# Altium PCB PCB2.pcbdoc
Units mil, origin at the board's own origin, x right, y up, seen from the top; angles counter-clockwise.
Board outline 2783.42 x 2077.01 mil, 2 copper layers (Top Layer, Bottom Layer), stack 62.206 mil thick; 55 components, 70 nets, 239 pads, 88 vias.
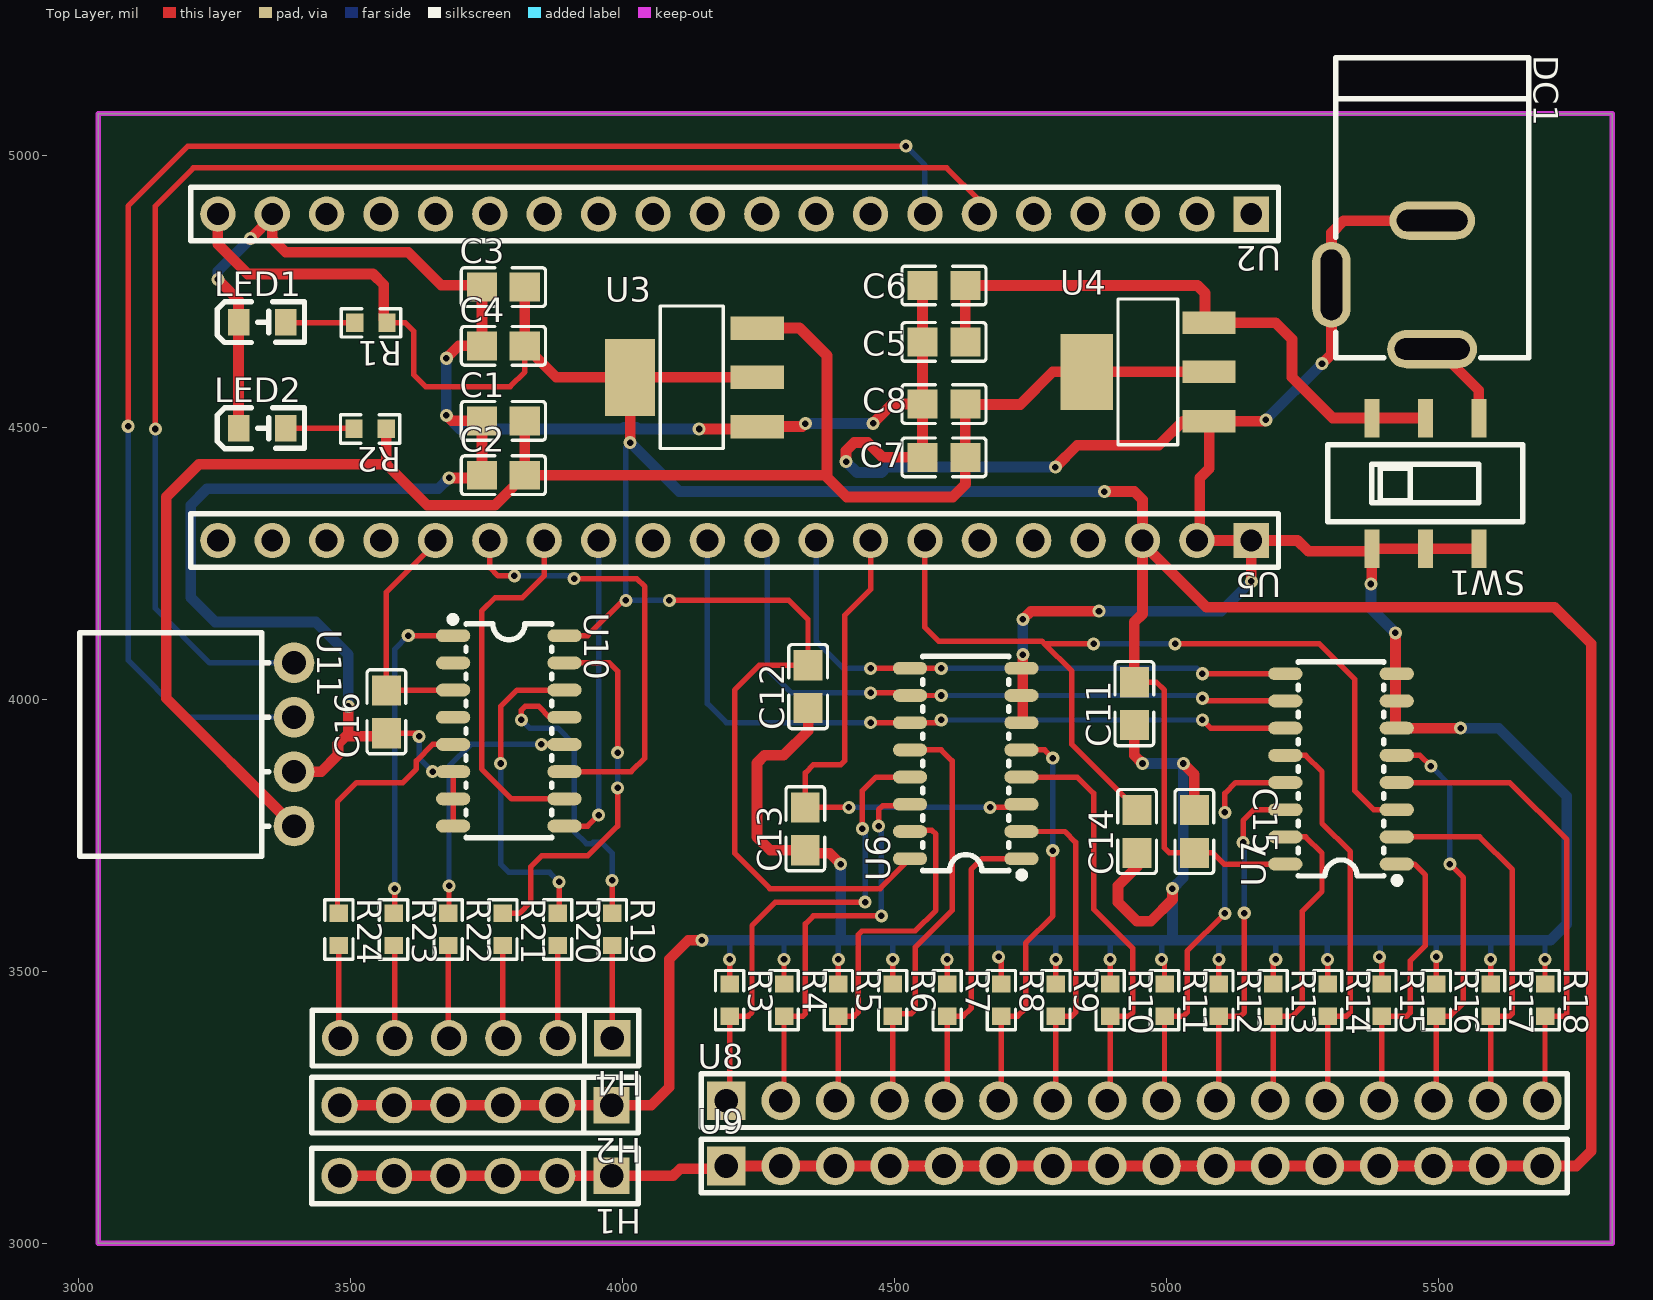
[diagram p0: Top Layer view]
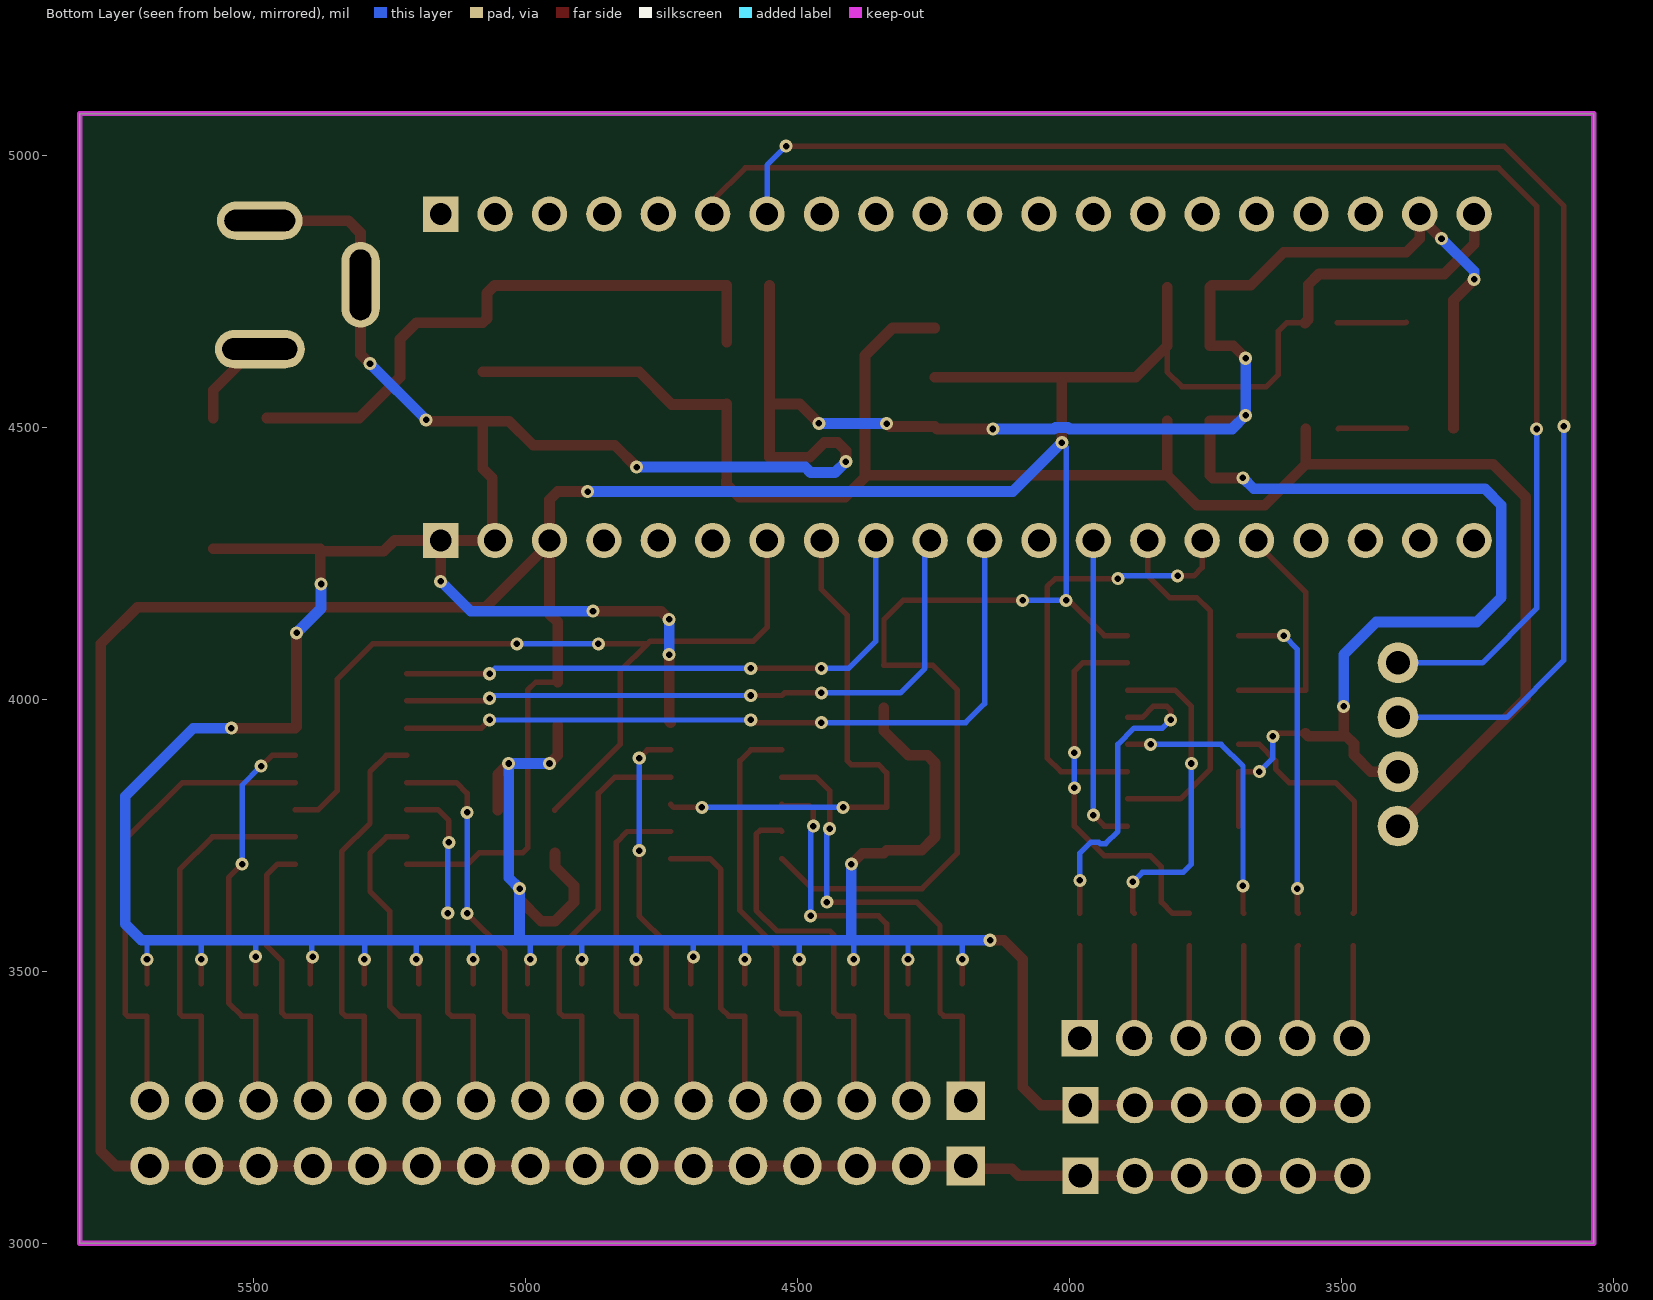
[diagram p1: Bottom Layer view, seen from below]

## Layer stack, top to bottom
Top Solder Mask Layer: solder mask 0.394, Dk 3.3
Top Layer: signal copper 1.379
Dielectric1: surface 59.449, FR4, Dk 4.5
Bottom Layer: signal copper 1.378
Bottom Solder Mask Layer: solder mask 0.394, Dk 3.3

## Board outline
3036.06,5077.01 3036.06,3000 5819.48,3000 5819.48,5077.01

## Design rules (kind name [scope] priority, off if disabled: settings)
BoardOutlineClearance copperThickness1oz [All] p0: genericclearance=10 ignorepadtopadclearanceinfootprint=FALSE except(0: Arc-SplitContinuation Track-SplitContinuation SMDPad-SplitContinuation THPad-SplitContinuation Via-SplitContinuation Fill-SplitContinuation Poly-SplitContinuation Region-SplitContinuation Text-SplitContinuation)
BoardOutlineClearance copperThickness2oz [All] p0: genericclearance=10 ignorepadtopadclearanceinfootprint=FALSE except(0: Arc-SplitContinuation Track-SplitContinuation SMDPad-SplitContinuation THPad-SplitContinuation Via-SplitContinuation Fill-SplitContinuation Poly-SplitContinuation Region-SplitContinuation Text-SplitContinuation)
BoardOutlineClearance otherClearance [All] p0: genericclearance=10 ignorepadtopadclearanceinfootprint=FALSE except(0: Arc-SplitContinuation Track-SplitContinuation SMDPad-SplitContinuation THPad-SplitContinuation Via-SplitContinuation Fill-SplitContinuation Poly-SplitContinuation Region-SplitContinuation Text-SplitContinuation)
Clearance copperThickness1oz [All] p1: gap=7 ignorepadtopadclearanceinfootprint=FALSE
Clearance copperThickness2oz [All] p1: gap=7 ignorepadtopadclearanceinfootprint=FALSE
Clearance otherClearance [All] p1: gap=7 ignorepadtopadclearanceinfootprint=FALSE
DiffPairsRouting differentialPair [All] p1: maxuncoupledlength=10 minlimit=6 maxlimit=Infinity mostfreqgap=6 toplayer_minwidth=5 toplayer_prefwidth=10 toplayer_maxwidth=100 bottomlayer_minwidth=5 bottomlayer_prefwidth=10 bottomlayer_maxwidth=100
PasteMaskExpansion pasteMaskExpansion [All] p1: expansion=0
PlaneConnect innerPlane [All] p1: planeconnectstyle=Relief reliefexpansion=20 reliefentries=4 reliefconductorwidth=10 reliefairgap=10
PolygonConnect copperRegion [All] p1: connectstyle=Relief reliefentries=4 reliefconductorwidth=10 polygonreliefangle="90 Angle" airgapwidth=10
RoutingVias viaSize [All] p1: viastyle="Through Hole" holewidth=12.0078 minholewidth=11.811 maxholewidth=248.0314 width=12.0078 minwidth=11.811 maxwidth=248.0314
SolderMaskExpansion solderMaskExpansion [IsVia] p1: useseparateexpansions=TRUE expansion=-1000 expansionbottom=-1000
SolderMaskExpansion solderMaskExpansion [All] p2: useseparateexpansions=TRUE expansion=2 expansionbottom=2
Width copperThickness1oz [All] p1: maxlimit=100 minlimit=5 preferedwidth=10
Width copperThickness2oz [All] p1: maxlimit=100 minlimit=8 preferedwidth=10

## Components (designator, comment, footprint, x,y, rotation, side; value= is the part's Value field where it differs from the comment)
C1 "10uF" C0805 3781.06,4512.01 r0 top
C2 "100nF" C0805 3781.06,4412.01 r0 top
C3 "10uF" C0805 3781.06,4757.86 r0 top
C4 "100nF" C0805 3781.06,4649.93 r0 top
C5 "10uF" C0805 4591.06,4657.01 r0 top
C6 "100nF" C0805 4591.06,4760.78 r0 top
C7 "10uF" C0805 4591.06,4444.93 r0 top
C8 "100nF" C0805 4591.06,4542.86 r0 top
C11 "10nF" C0805 4941.06,3992.01 r90 top
C12 "10nF" C0805 4341.37,4023.33 r90 top
C13 "10nF" C0805 4336.06,3762.01 r90 top
C14 "10nF" C0805 4946.06,3757.01 r90 top
C15 "100nF" C0805 5051.38,3756.93 r270 top
C16 "100nF" C0805 3566.06,3977.01 r90 top
DC1 "DC-005-5A-2.0" DC-IN-TH_DC-005-5A-2.0 5396.06,4762.01 r270 top
H1 "PZ254V-11-06P" HDR-TH_6P-P2.54-V-M 3729.86,3123.84 r180 top
H2 "PZ254V-11-06P" HDR-TH_6P-P2.54-V-M 3729.86,3253.84 r180 top
H4 "PZ254V-11-06P" HDR-TH_6P-P2.54-V-M 3731.06,3377.01 r180 top
LED1 "" LED_0805 3339.43,4693.25 r0 top
LED2 "" LED_0805 3339.43,4498.25 r0 top
R1 "1K" R0603 3537.57,4692.01 r180 top
R2 "1K" R0603 3536.06,4497.01 r180 top
R3 "24K" R0603 4197.01,3447.09 r270 top
R4 "24K" R0603 4296.95,3447.09 r270 top
R5 "24K" R0603 4396.89,3447.09 r270 top
R6 "24K" R0603 4496.82,3447.09 r270 top
R7 "24K" R0603 4596.76,3447.09 r270 top
R8 "24K" R0603 4696.7,3447.09 r270 top
R9 "24K" R0603 4796.63,3447.09 r270 top
R10 "24K" R0603 4896.57,3447.09 r270 top
R11 "24K" R0603 4996.51,3447.09 r270 top
R12 "24K" R0603 5096.44,3447.09 r270 top
R13 "24K" R0603 5196.38,3447.09 r270 top
R14 "24K" R0603 5296.32,3447.09 r270 top
R15 "24K" R0603 5396.25,3447.09 r270 top
R16 "24K" R0603 5496.19,3447.09 r270 top
R17 "24K" R0603 5596.12,3447.09 r270 top
R18 "24K" R0603 5696.06,3447.09 r270 top
R19 "1K" R0603 3981.37,3576.86 r270 top
R20 "1K" R0603 3880.78,3576.86 r270 top
R21 "1K" R0603 3780.19,3576.86 r270 top
R22 "1K" R0603 3679.6,3576.86 r270 top
R23 "1K" R0603 3579.01,3576.86 r270 top
R24 "1K" R0603 3478.41,3576.86 r270 top
SW1 "SS-3235S-L1" SW-SMD_SS-3235S-LX 5476.06,4397.01 r180 top
U2 "KH-2.54FH-1X20P-H8.5" HDR-TH_20P-P2.54-V-F-2 4206.06,4892.01 r180 top
U3 "AMS1117-3.3" SOT-223-3_L6.5-W3.4-P2.30-LS7.0-BR 4131.06,4592.01 r0 top
U4 "AMS1117-5.0" SOT-223_L6.5-W3.5-P2.30-LS7.0-BR 4966.06,4602.01 r0 top
U5 "KH-2.54FH-1X20P-H8.5" HDR-TH_20P-P2.54-V-F-2 4206.06,4292.01 r180 top
U6 "CD4051BM/TR" SOP-16_L9.9-W3.9-P1.27-LS6.1-BL 4631.06,3882.01 r90 top
U7 "CD4051BM/TR" SOP-16_L9.9-W3.9-P1.27-LS6.1-BL 5321.06,3872.01 r90 top
U8 "ZX-PZ2.54-1-16PZZ" HDR-TH_16P-P2.54-V-M-2 4941.06,3262.01 r0 top
U9 "ZX-PZ2.54-1-16PZZ" HDR-TH_16P-P2.54-V-M-2 4941.06,3142.01 r0 top
U10 "CD4051BM/TR" SOP-16_L9.9-W3.9-P1.27-LS6.1-BL 3791.06,3942.01 r270 top
U11 "PM254-1-04-W-8.5" HDR-TH_4P-P2.54-H-F-W10.0-N 3396.06,3917.01 r270 top

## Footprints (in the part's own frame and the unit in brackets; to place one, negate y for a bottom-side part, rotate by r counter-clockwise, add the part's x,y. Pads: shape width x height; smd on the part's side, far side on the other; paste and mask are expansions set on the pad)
C0805 [mm]
  rect 1.41x1.35 smd paste-100 mask+0.051: 1(-1,0) 2(1,0)
  silkscreen extent -1.96,-0.9 1.96,0.9
DC-IN-TH_DC-005-5A-2.0 [mm]
  oval 1.8x4.2 hole 1 slot 3.5 at 90 deg: 1(3,2.352)
  oval 1.8x4 hole 1 slot 3.3 at 90 deg: 2(-3,2.352)
  oval 4x1.8 hole 1 slot 3.3 at 0 deg: 3(0,-2.352)
  silkscreen extent -10.6,-2.15 3.4,6.85
HDR-TH_4P-P2.54-H-F-W10.0-N [mm]
  round 1.9 hole 1.1 paste+0 mask+0.05: 1(-3.81,0) 2(-1.27,0) 3(1.27,0) 4(3.81,0)
  silkscreen extent -5.22,-10 5.22,-1.18
HDR-TH_6P-P2.54-V-M [mm]
  rect 1.7x1.7 hole 1.1: 1(-6.35,0)
  round 1.7 hole 1.1: 2(-3.81,0) 3(-1.27,0) 4(1.27,0) 5(3.81,0) 6(6.35,0)
  silkscreen extent -7.6,-1.3 7.65,1.3
HDR-TH_16P-P2.54-V-M-2 [mm]
  rect 1.8x1.8 hole 1.1: 1(-19.05,0)
  round 1.8 hole 1.1: 2(-16.51,0) 3(-13.97,0) 4(-11.43,0) 5(-8.89,0) 6(-6.35,0) 7(-3.81,0) 8(-1.27,0) 9(1.27,0) 10(3.81,0) 11(6.35,0) 12(8.89,0) 13(11.43,0) 14(13.97,0) 15(16.51,0) 16(19.05,0)
  silkscreen extent -20.22,-1.25 20.22,1.25
HDR-TH_20P-P2.54-V-F-2 [mm]
  rect 1.65x1.65 hole 1.02: 1(-24.13,0)
  round 1.65 hole 1.02: 2(-21.59,0) 3(-19.05,0) 4(-16.51,0) 5(-13.97,0) 6(-11.43,0) 7(-8.89,0) 8(-6.35,0) 9(-3.81,0) 10(-1.27,0) 11(1.27,0) 12(3.81,0) 13(6.35,0) 14(8.89,0) 15(11.43,0) 16(13.97,0) 17(16.51,0) 18(19.05,0) 19(21.59,0) 20(24.13,0)
  silkscreen extent -25.4,-1.25 25.4,1.25
LED_0805 [mm]
  rect 1x1.25 smd paste+0 mask+0.051: 1(-1.15,0.005) 2(1.05,0.005)
  silkscreen extent -2.15,-0.94 1.93,0.97
R0603 [mil]
  rect 31.75x34.02 smd paste-3937.01 mask+2: 1(-29.66,0) 2(29.66,0)
  silkscreen extent -55,-26 55,26
SOP-16_L9.9-W3.9-P1.27-LS6.1-BL [mm]
  oval 0.6x1.6 smd: 1(-4.445,-2.6) 2(-3.175,-2.6) 3(-1.905,-2.6) 4(-0.635,-2.6) 5(0.635,-2.6) 6(1.905,-2.6) 7(3.175,-2.6) 8(4.445,-2.6) 9(4.445,2.6) 10(3.175,2.6) 11(1.905,2.6) 12(0.635,2.6) 13(-0.635,2.6) 14(-1.905,2.6) 15(-3.175,2.6) 16(-4.445,2.6)
  silkscreen extent -5.36,-2.76 5,2
SOT-223-3_L6.5-W3.4-P2.30-LS7.0-BR [mm]
  rect 2.5x1.1 smd: 1(2.97,-2.3) 2(2.97,0) 3(2.97,2.3)
  rect 2.34x3.6 smd: 4(-2.97,0)
  silkscreen extent -1.57,-3.33 1.37,3.33
SOT-223_L6.5-W3.5-P2.30-LS7.0-BR [mm]
  rect 2.465x1.05 smd: 1(2.857,-2.3) 2(2.857,0) 3(2.857,2.3)
  rect 2.465x3.54 smd: 4(-2.857,0)
  silkscreen extent -1.4,-3.4 1.4,3.4
SW-SMD_SS-3235S-LX [mm]
  rect 0.7x1.8 smd: 1(-2.5,3.05) 2(0,3.05) 3(2.5,3.05) 4(-2.5,-3.05) 5(0,-3.05) 6(2.5,-3.05)
  silkscreen extent -4.55,-1.8 4.55,1.8

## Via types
v1: diameter 24.02, hole 12, Top Layer to Bottom Layer, 88 vias

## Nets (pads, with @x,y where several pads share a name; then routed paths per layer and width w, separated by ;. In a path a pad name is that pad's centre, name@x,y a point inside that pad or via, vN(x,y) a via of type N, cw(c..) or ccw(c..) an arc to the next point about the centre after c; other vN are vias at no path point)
$1N1602: LED2.2 R2.2 | length 126.2
  Top Layer w10: LED2.2 3504.95,4498.45 R2.2
$1N1617: LED1.2 R1.2 | length 127.7
  Top Layer w10: LED1.2 3382.22,4692.01 R1.2
$1N7376: H4.1 R19.2 | length 170.3
  Top Layer w10: H4.1 3981.37,3377.32 R19.2
$1N7377: H4.2 R20.2 | length 170.3
  Top Layer w10: R20.2 3880.78,3377.29 H4.2
$1N7378: H4.3 R21.2 | length 170.6
  Top Layer w10: R21.2 3780.19,3377.88 H4.3
$1N7379: H4.4 R22.2 | length 170.8
  Top Layer w10: R22.2 3679.6,3378.47 H4.4
$1N7380: H4.5 R23.2 | length 171
  Top Layer w10: R23.2 3581.06,3545.14 H4.5
$1N7381: H4.6 R24.2 | length 171.3
  Top Layer w10: R24.2 3478.41,3379.65 H4.6
$1N7401: U10.4
+3.3V: C3.2 C4.2 C11.2 C12.2 C15.2 H1.1 H1.2 H1.3 H1.4 H1.5 H1.6 R1.1 U2.20 U3.2 U3.4 U5.3 U6.16 U7.16 U9.1 U9.2 U9.3 U9.4 U9.5 U9.6 U9.7 U9.8 U9.9 U9.10 U9.11 U9.12 U9.13 U9.14 U9.15 U9.16 U10.16 | length 9312
  Top Layer w10: R1.1 3601.06,4692.01 3616.06,4677.01 3616.06,4597.01 3638.25,4574.82 3793.25,4574.82 3820.43,4602.01 C4.2 ; U10.16 3936.06,4117.01 4001.06,4182.01 v1(4006.06,4182.01) ; v1(4086.06,4182.01) 4306.06,4182.01 4341.06,4147.01 4341.06,4063.01 C12.2 4251.76,4062.7 4206.06,4017.01 4206.06,3717.01 4271.06,3652.01 4473.7,3652.01 U6.16 ; C11.2 4981.69,4031.38 4996.06,4017.01 4996.06,3727.01 5005.51,3717.56 C15.2 5085.51,3717.56 5106.06,3697.01 U7.16
  Top Layer w19.68: U2.20 3256.06,4837.01 3311.06,4782.01 3541.38,4782.01 3561.06,4762.32 3561.06,4698.17 R1.1 ; H1.6 H1.5 H1.4 H1.3 H1.2 H1.1 4092.89,3123.84 4106.06,3137.01 4186.06,3137.01 U9.1 U9.2 U9.3 U9.4 U9.5 U9.6 U9.7 U9.8 U9.9 U9.10 U9.11 U9.12 U9.13 U9.14 U9.15 U9.16 5753.56,3142.01 5781.06,3169.51 5781.06,4102.01 5713.56,4169.51 5073.56,4169.51 U5.3@4956.06,4287.01 ; C3.2 C4.2 3878.36,4592.01 U3.4 ; v1(4014.13,4472.01) U3.4 ; U3.2 U3.4 ; v1(4886.06,4382.01) 4941.06,4382.01 4956.06,4367.01 U5.3 U5.3@4956.06,4287.01 ; C11.2 4941.06,4142.01 4956.06,4157.01 U5.3@4956.06,4287.01
  Bottom Layer w10: v1(4014.13,4472.01) 4006.06,4463.94 v1(4006.06,4182.01) v1(4086.06,4182.01)
  Bottom Layer w19.68: v1(4014.13,4472.01) 4104.13,4382.01 v1(4886.06,4382.01)
+5V: C1.2 C2.2 C7.2 C8.2 R2.1 U3.3 U4.2 U4.4 U11.4 | length 3435.6
  Top Layer w19.68: U11.4 3161.06,4002.01 3161.06,4372.01 3221.4,4432.35 3565.72,4432.35 ; R2.1 3565.72,4432.35 ; C1.2 C2.2 ; U3.3 4325.51,4682.56 4376.06,4632.01 4376.06,4408.4 ; U4.2 U4.4 4791.06,4602.01 4731.06,4542.01 4631.28,4542.01 C8.2 C7.2 4630.43,4402.64 4631.06,4402.01 4631.06,4395.93 4607.14,4372.01 4412.46,4372.01 4376.06,4408.4 ; 3565.72,4432.35 3641.06,4357.01 3765.43,4357.01 C2.2 ; C2.2 4372.46,4412.01 4376.06,4408.4
+9V: C5.2 C6.2 SW1.5 SW1.6 U4.3 | length 1119
  Top Layer w19.68: C5.2 C6.2 4630.57,4760.93 5057.14,4760.93 5071.06,4747.01 5071.06,4700.06 U4.3 5200.51,4692.56 5231.06,4662.01 5231.06,4592.01 5305.98,4517.09 SW1.6 SW1.5
+9V-BATTERY: DC1.1 SW1.4 | length 165.3
  Top Layer w19.68: DC1.1@5493.65,4648.9 5574.49,4568.06 SW1.4
GND: C1.1 C2.1 C3.1 C4.1 C5.1 C6.1 C7.1 C8.1 C11.1 C12.1 C13.1 C14.1 C15.1 C16.1 DC1.2 DC1.3 H2.1 H2.2 H2.3 H2.4 H2.5 H2.6 LED1.1 LED2.1 R3.1 R4.1 R5.1 R6.1 R7.1 R8.1 R9.1 R10.1 R11.1 R12.1 R13.1 R14.1 R15.1 R16.1 R17.1 R18.1 SW1.1 SW1.2 SW1.3 U2.19 U3.1 U4.1 U5.1 U5.2 U6.6 U6.7 U6.8 U7.6 U7.7 U7.8 U10.6 U10.7 U10.8 U11.3 | length 13582.8
  Top Layer w10: C16.1 3620.43,3937.64 v1(3626.06,3932.01) ; v1(3651.06,3867.01) U10.6 U10.7 U10.8 ; R3.1 v1(4197.01,3522.01) ; R4.1 v1(4296.95,3522.01) ; R5.1 v1(4396.89,3522.01) ; R6.1 v1(4496.82,3522.01) ; R7.1 v1(4596.76,3522.01) ; v1(4691.49,3526.58) 4696.7,3521.37 R8.1 ; R9.1 v1(4796.63,3522.01) ; R10.1 v1(4896.57,3522.01) ; v1(4991.06,3522.01) 4996.51,3516.56 R11.1 ; R12.1 v1(5096.44,3522.01) ; R13.1 5196.38,3517.33 v1(5201.06,3522.01) ; R14.1 v1(5296.32,3522.01) ; v1(5391.49,3526.58) 5396.25,3521.82 R15.1 ; R16.1 v1(5496.19,3527.01) ; R17.1 v1(5596.12,3522.01) ; R18.1 v1(5696.06,3522.01)
  Top Layer w19.68: v1(3256.06,4772.01) 3294.15,4733.92 LED1.1 LED2.1 ; v1(3316.06,4847.01) U2.19@3356.06,4887.01 ; U2.19 U2.19@3356.06,4887.01 ; U11.3 3446.06,3867.01 3477.14,3898.09 3477.14,3918.09 3491.06,3932.01 3499.41,3932.01 ; H2.6 H2.5 H2.4 H2.3 H2.2 H2.1 4052.89,3253.84 4086.06,3287.01 4086.06,3522.01 4121.06,3557.01 v1(4146.06,3557.01) ; v1(3496.06,3987.01) 3496.06,3935.36 3499.41,3932.01 ; C16.1 3560.43,3932.01 3499.41,3932.01 ; v1(3676.06,4522.01) 3686.06,4512.01 C1.1 C2.1 3736.69,4407.01 v1(3681.06,4407.01) ; v1(3676.06,4627.01) 3698.99,4649.93 C4.1 C3.1 3738.19,4761.36 3666.71,4761.36 3606.06,4822.01 3381.06,4822.01 3356.06,4847.01 U2.19@3356.06,4887.01 ; v1(4141.06,4497.01) 4243.54,4497.01 U3.1 4330.51,4501.46 v1(4336.06,4507.01) ; C12.1 4341.37,3942.31 4296.06,3897.01 4261.06,3897.01 4247.14,3883.09 4247.14,3747.01 4271.51,3722.64 C13.1 4341.69,3717.01 4381.06,3717.01 v1(4401.06,3697.01) ; v1(4411.06,4437.01) 4411.06,4457.01 4426.06,4472.01 4451.06,4472.01 4478.14,4444.93 C7.1 C8.1 ; v1(4460.64,4507.43) 4496.06,4542.86 C8.1 ; C6.1 C5.1 C8.1 ; U6.6 4736.06,3959.64 v1(4736.06,4082.01) ; v1(4736.06,4147.01) 4751.06,4162.01 v1(4876.06,4162.01) ; v1(4796.06,4427.01) 4836.06,4467.01 4986.06,4467.01 5030.51,4511.46 U4.1 ; C11.1 4941.06,3897.01 v1(4956.06,3882.01) ; C14.1 4946.06,3692.01 4911.06,3657.01 4911.06,3627.01 4946.06,3592.01 4971.06,3592.01 5011.06,3632.01 v1(5011.06,3652.01) ; v1(5031.06,3882.01) 5051.38,3861.69 C15.1 ; v1(5156.06,4217.01) U5.1 ; v1(5182.8,4513.74) 5180.51,4511.46 U4.1 ; v1(5286.06,4617.01) 5303.48,4634.42 DC1.3 5303.48,4857.53 5326.06,4880.12 DC1.2 ; v1(5376.06,4212.01) 5377.64,4213.58 SW1.3 ; v1(5421.06,4122.01) 5421.06,3949.37 U7.6 v1(5541.06,3947.01) ; SW1.1 SW1.2 SW1.3 ; U4.1 5078.56,4424.51 5061.06,4407.01 5061.06,4297.01 U5.2 U5.1 ; U5.1 5241.06,4292.01 5261.06,4272.01 5372.72,4272.01 SW1.3
  Bottom Layer w10: v1(3626.06,3932.01) 3626.06,3892.01 v1(3651.06,3867.01) ; v1(4197.01,3522.01) 4197.01,3555.43 4198.59,3557.01 ; 4296.21,3557.01 4296.95,3556.26 v1(4296.95,3522.01) ; 4395.5,3557.01 4396.89,3555.62 v1(4396.89,3522.01) ; 4496.45,3557.01 4496.82,3556.64 v1(4496.82,3522.01) ; 4596.58,3557.01 4596.76,3556.82 v1(4596.76,3522.01) ; 4690.86,3557.01 4691.49,3556.38 v1(4691.49,3526.58) ; 4795.99,3557.01 4796.63,3556.36 v1(4796.63,3522.01) ; v1(4896.57,3522.01) 4896.57,3554.96 4898.61,3557.01 ; v1(4991.06,3522.01) 4991.06,3555.17 4992.9,3557.01 ; v1(5096.44,3522.01) 5096.44,3556.26 5097.19,3557.01 ; 5198.98,3557.01 5201.06,3554.93 v1(5201.06,3522.01) ; 5295.77,3557.01 5295.77,3522.56 v1(5296.32,3522.01) ; v1(5391.49,3526.58) 5393.39,3528.48 5393.39,3557.01 ; 5495.18,3557.01 5496.19,3556 v1(5496.19,3527.01) ; v1(5596.12,3522.01) 5596.12,3556.16 5596.97,3557.01 ; 5694.59,3557.01 5696.06,3555.54 v1(5696.06,3522.01)
  Bottom Layer w19.68: v1(3256.06,4772.01) 3256.06,4787.01 v1(3316.06,4847.01) ; v1(3496.06,3987.01) 3496.06,4082.01 3436.06,4142.01 3251.06,4142.01 3206.06,4187.01 3206.06,4357.01 3236.06,4387.01 3661.06,4387.01 v1(3681.06,4407.01) ; v1(3676.06,4627.01) v1(3676.06,4522.01) 3701.06,4497.01 3999.77,4497.01 4002.6,4499.84 4025.66,4499.84 4028.5,4497.01 v1(4141.06,4497.01) ; v1(4146.06,3557.01) 4198.59,3557.01 4296.21,3557.01 4395.5,3557.01 4404.48,3557.01 ; v1(4336.06,4507.01) 4460.21,4507.01 v1(4460.64,4507.43) ; v1(4401.06,3697.01) 4401.06,3560.42 4404.48,3557.01 ; v1(4411.06,4437.01) 4431.06,4417.01 4476.06,4417.01 4486.06,4427.01 v1(4796.06,4427.01) ; v1(4736.06,4082.01) v1(4736.06,4147.01) ; v1(4876.06,4162.01) 5101.06,4162.01 v1(5156.06,4217.01) ; v1(4956.06,3882.01) v1(5031.06,3882.01) 5031.06,3672.01 v1(5011.06,3652.01) 5011.06,3557.95 5012,3557.01 ; v1(5182.8,4513.74) v1(5286.06,4617.01) ; v1(5376.06,4212.01) 5376.06,4167.01 v1(5421.06,4122.01) ; v1(5541.06,3947.01) 5611.06,3947.01 5736.06,3822.01 5736.06,3587.01 5706.06,3557.01 5694.59,3557.01 5596.97,3557.01 5495.18,3557.01 5393.39,3557.01 5295.77,3557.01 5198.98,3557.01 5097.19,3557.01 5012,3557.01 ; 4404.48,3557.01 4496.45,3557.01 4596.58,3557.01 4690.86,3557.01 4795.99,3557.01 4898.61,3557.01 4992.9,3557.01 5012,3557.01
H0: R3.2 U6.13 U8.1 | length 892.3
  Top Layer w10: U8.1 4197.01,3267.96 R3.2 4231.06,3417.43 4238.13,3424.5 4238.13,3584.08 4281.06,3627.01 v1(4446.06,3627.01) ; v1(4441.06,3762.01) 4441.06,3832.01 4466.06,3857.01 U6.13
  Bottom Layer w10: v1(4441.06,3762.01) 4446.06,3757.01 v1(4446.06,3627.01)
H1: R4.2 U6.14 U8.2 | length 768.9
  Top Layer w10: U8.2 4296.95,3267.9 R4.2 4331.48,3417.43 4336.06,3422.01 4336.06,3587.01 4351.06,3602.01 v1(4476.06,3602.01) ; v1(4471.06,3767.01) 4471.06,3797.01 4478.13,3804.08 4525.77,3804.08 U6.14
  Bottom Layer w10: v1(4471.06,3767.01) 4476.06,3762.01 v1(4476.06,3602.01)
H2: R5.2 U6.15 U8.3 | length 692.2
  Top Layer w10: U8.3 4396.89,3267.83 R5.2 4426.06,3417.43 4433.13,3424.5 4433.13,3567.01 4440.2,3574.08 4538.13,3574.08 4576.06,3612.01 4576.06,3752.01 4568.99,3759.08 4530.77,3759.08 U6.15
H3: R6.2 U6.12 U8.4 | length 775.4
  Top Layer w10: U8.4 4496.82,3267.77 R6.2 4501.41,3422.01 4531.06,3422.01 4538.13,3429.08 4538.13,3544.08 4605.87,3611.82 4605.87,3887.01 4585.87,3907.01 U6.12
H4: R7.2 U6.1 U8.5 | length 563.8
  Top Layer w10: U8.5 4596.76,3267.71 R7.2 4626.48,3417.43 4641.06,3432.01 4641.06,3687.01 4661.06,3707.01 U6.1
H5: R8.2 U6.5 U8.6 | length 752.7
  Top Layer w10: U8.6 4696.7,3267.64 R8.2 4726.48,3417.43 4741.06,3432.01 4741.06,3552.01 4791.06,3602.01 v1(4791.06,3722.01) ; U6.5 4776.06,3907.01 v1(4791.06,3892.01)
  Bottom Layer w10: v1(4791.06,3722.01) v1(4791.06,3892.01)
H6: R9.2 U6.2 U8.7 | length 617.7
  Top Layer w10: U6.2 4813.13,3757.01 4833.13,3737.01 4833.13,3424.5 4826.06,3417.43 R9.2 4796.63,3267.58 U8.7
H7: R10.2 U6.4 U8.8 | length 779.6
  Top Layer w10: U6.4 4836.06,3857.01 4866.06,3827.01 4866.06,3614.08 4938.13,3542.01 4938.13,3424.5 4931.06,3417.43 R10.2 4896.57,3267.52 U8.8
H8: R11.2 U7.13 U8.9 | length 753
  Top Layer w10: U8.9 4996.51,3267.45 R11.2 5031.06,3417.43 5038.13,3424.5 5038.13,3537.01 v1(5107.46,3606.34) ; v1(5107.46,3792.01) 5107.46,3827.01 5127.46,3847.01 U7.13
  Bottom Layer w10: v1(5107.46,3606.34) v1(5107.46,3792.01)
H9: R12.2 U7.14 U8.10 | length 646.6
  Top Layer w10: U8.10 5096.44,3267.39 R12.2 5136.06,3417.43 5143.13,3424.5 v1(5143.13,3607.01) ; v1(5141.06,3737.01) 5141.06,3777.01 5161.06,3797.01 U7.14
  Bottom Layer w10: v1(5141.06,3737.01) 5143.13,3734.94 v1(5143.13,3607.01)
H10: R13.2 U7.15 U8.11 | length 594.7
  Top Layer w10: U8.11 5196.38,3267.33 R13.2 5231.48,3417.43 5249.78,3435.72 5249.78,3610.72 5286.06,3647.01 5286.06,3717.01 5256.06,3747.01 U7.15
H11: R14.2 U7.12 U8.12 | length 746.2
  Top Layer w10: U7.12 5256.06,3897.01 5286.06,3867.01 5286.06,3772.01 5338.13,3719.94 5338.13,3424.5 5331.06,3417.43 R14.2 5296.32,3267.26 U8.12
H12: R15.2 U7.1 U8.13 | length 538
  Top Layer w10: U8.13 5396.25,3267.2 R15.2 5430.64,3417.43 5431.06,3417.01 5441.06,3417.01 5448.13,3424.08 5448.13,3519.08 5476.06,3547.01 5476.06,3677.01 5456.06,3697.01 U7.1
H13: R16.2 U7.5 U8.14 | length 748.4
  Top Layer w10: U7.5 5466.06,3897.01 v1(5486.06,3877.01) ; U8.14 5496.19,3267.14 R16.2 5521.48,3417.43 5546.06,3442.01 5546.06,3672.01 v1(5521.06,3697.01)
  Bottom Layer w10: v1(5486.06,3877.01) 5521.06,3842.01 v1(5521.06,3697.01)
H14: R17.2 U7.2 U8.15 | length 701.8
  Top Layer w10: U7.2 5576.06,3747.01 5636.06,3687.01 5636.06,3422.01 5631.48,3417.43 R17.2 5596.12,3267.07 U8.15
H15: R18.2 U7.4 U8.16 | length 875.5
  Top Layer w10: U7.4 5631.06,3847.01 5736.06,3742.01 5736.06,3422.01 5731.48,3417.43 R18.2 5696.06,3267.01 U8.16
HZ0: R19.1 U10.13 | length 583.5
  Top Layer w10: v1(3813.99,3962.01) 3813.99,3979.94 3821.06,3987.01 3846.06,3987.01 3866.06,3967.01 U10.13 ; v1(3981.06,3667.01) 3981.06,3606.83 R19.1
  Bottom Layer w10: v1(3813.99,3962.01) 3828.99,3947.01 3881.06,3947.01 3911.06,3917.01 3911.06,3757.01 3933.56,3734.51 3943.56,3734.51 3946.06,3737.01 3961.06,3737.01 3981.06,3717.01 v1(3981.06,3667.01)
HZ1: R20.1 U10.14 | length 599.9
  Top Layer w10: v1(3776.06,3882.01) 3776.06,3987.01 3806.06,4017.01 U10.14 ; R20.1 3883.56,3609.3 v1(3883.56,3664.51)
  Bottom Layer w10: v1(3776.06,3882.01) 3776.06,3697.01 3791.06,3682.01 3866.06,3682.01 v1(3883.56,3664.51)
HZ2: R21.1 U10.15 | length 704.3
  Top Layer w10: R21.1 3810.57,3606.52 3831.06,3627.01 3831.06,3692.01 3851.06,3712.01 3936.06,3712.01 3991.06,3767.01 v1(3991.06,3837.01) ; U10.15 3976.06,4067.01 3991.06,4052.01 v1(3991.06,3902.01)
  Bottom Layer w10: v1(3991.06,3837.01) v1(3991.06,3902.01)
HZ3: R22.1 U10.12 | length 500
  Top Layer w10: R22.1 3681.06,3607.98 v1(3681.06,3657.01) ; v1(3851.06,3917.01) U10.12
  Bottom Layer w10: v1(3681.06,3657.01) 3681.06,3877.01 3721.06,3917.01 v1(3851.06,3917.01)
HZ4: R23.1 U10.1 | length 604.3
  Top Layer w10: R23.1 3581.06,3608.57 v1(3581.06,3652.01) ; v1(3606.06,4117.01) U10.1
  Bottom Layer w10: v1(3581.06,3652.01) 3581.06,4092.01 v1(3606.06,4117.01)
HZ5: R24.1 U10.5 | length 471.4
  Top Layer w10: R24.1 3476.06,3608.87 3476.06,3812.01 3511.06,3847.01 3596.06,3847.01 3621.06,3872.01 3621.06,3887.01 3651.06,3917.01 U10.5
HZ6: U10.2
PA0: C16.2 U5.16 U10.3 | length 435.8
  Top Layer w10: U5.16 3656.06,4287.01 3566.06,4197.01 C16.2 3688.07,4016.38 U10.3
PA1: U5.15 U10.11 | length 822.5
  Top Layer w10: U5.15 3756.06,4242.01 3771.06,4227.01 v1(3801.06,4227.01) ; U10.11 4016.06,3867.01 4041.06,3892.01 4041.06,4207.01 4026.06,4222.01 v1(3911.06,4222.01)
  Bottom Layer w10: v1(3801.06,4227.01) 3906.06,4227.01 v1(3911.06,4222.01)
PA2: U5.14 U10.10 | length 672.1
  Top Layer w10: U5.14 3856.06,4227.01 3816.06,4187.01 3766.06,4187.01 3741.06,4162.01 3741.06,3872.01 3796.06,3817.01 U10.10
PA3: U5.13 U10.9 | length 575.9
  Top Layer w10: U10.9 3936.06,3767.01 v1(3956.06,3787.01)
  Bottom Layer w10: v1(3956.06,3787.01) U5.13
PA4: U5.12
PA5: U5.11 U6.11 U7.11 | length 1385.4
  Top Layer w10: v1(4456.06,3957.01) U6.11 4581.06,3957.01 v1(4586.06,3962.01) ; v1(5066.06,3962.01) 5081.06,3947.01 U7.11
  Bottom Layer w10: U5.11 4156.06,3992.01 4191.06,3957.01 v1(4456.06,3957.01) ; v1(4586.06,3962.01) v1(5066.06,3962.01)
PA6: U5.10 U6.10 U7.10 | length 1216.6
  Top Layer w10: v1(4456.06,4012.01) 4523.7,4012.01 U6.10 v1(4586.06,4007.01) ; v1(5066.06,4002.01) 5071.06,3997.01 U7.10
  Bottom Layer w10: U5.10 4266.06,4282.01 4266.06,4057.01 4311.06,4012.01 v1(4456.06,4012.01) ; v1(4586.06,4007.01) 5061.06,4007.01 v1(5066.06,4002.01)
PA7: U5.9 U6.9 U7.9 | length 1072.5
  Top Layer w10: v1(4456.06,4057.01) U6.9 v1(4586.06,4057.01) ; v1(5066.06,4047.01) U7.9
  Bottom Layer w10: U5.9 4356.06,4107.01 4406.06,4057.01 v1(4456.06,4057.01) ; v1(4586.06,4057.01) 5056.06,4057.01 v1(5066.06,4047.01)
PA8: U2.5
PA9: U2.6 U11.1 | length 2630.3
  Top Layer w10: v1(3141.06,4497.01) 3141.06,4907.01 3211.06,4977.01 4596.06,4977.01 4656.06,4917.01 U2.6
  Bottom Layer w10: v1(3141.06,4497.01) 3141.06,4167.01 3241.06,4067.01 U11.1
PA10: U2.7 U11.2 | length 2798.6
  Top Layer w10: v1(3091.06,4502.01) 3091.06,4907.01 3201.06,5017.01 v1(4521.06,5017.01)
  Bottom Layer w10: v1(3091.06,4502.01) 3091.06,4072.01 3196.06,3967.01 U11.2 ; v1(4521.06,5017.01) 4556.06,4982.01 U2.7
PA11: U2.8
PA12: U2.9
PA15: U2.10
PB0: C13.2 U5.8 U6.3 | length 969.6
  Top Layer w10: v1(4416.06,3801.38) C13.2 4336.06,3864.94 4351.06,3879.94 4401.49,3879.94 4408.56,3887.01 4408.56,4154.51 4456.06,4202.01 U5.8 ; v1(4676.06,3801.38) 4727.8,3801.38 U6.3
  Bottom Layer w10: v1(4416.06,3801.38) v1(4676.06,3801.38)
PB1: C14.2 U5.7 U7.3 | length 1662.3
  Top Layer w10: U5.7 4556.06,4132.01 4581.06,4107.01 4771.06,4107.01 4776.06,4102.01 ; v1(4866.06,4102.01) 4776.06,4102.01 ; C14.2 4946.06,3797.01 4826.06,3917.01 4826.06,4052.01 4776.06,4102.01 ; v1(5016.06,4102.01) 5281.06,4102.01 5346.06,4037.01 5346.06,3832.01 5381.06,3797.01 U7.3
  Bottom Layer w10: v1(4866.06,4102.01) v1(5016.06,4102.01)
PB3: U2.11
PB4: U2.12
PB5: U2.13
PB6: U2.14
PB7: U2.15
PB8: U2.16
PB9: U2.17
PB10: U5.6
PB11: U5.5
PB12: U2.1
PB13: U2.2
PB14: U2.3
PB15: U2.4
PC13: U5.19
PC14: U5.18
PC15: U5.17
RESET: U5.4
pads on no net: U2.18 U5.20

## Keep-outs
Board Outline Layer:
  the board outline again, w10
